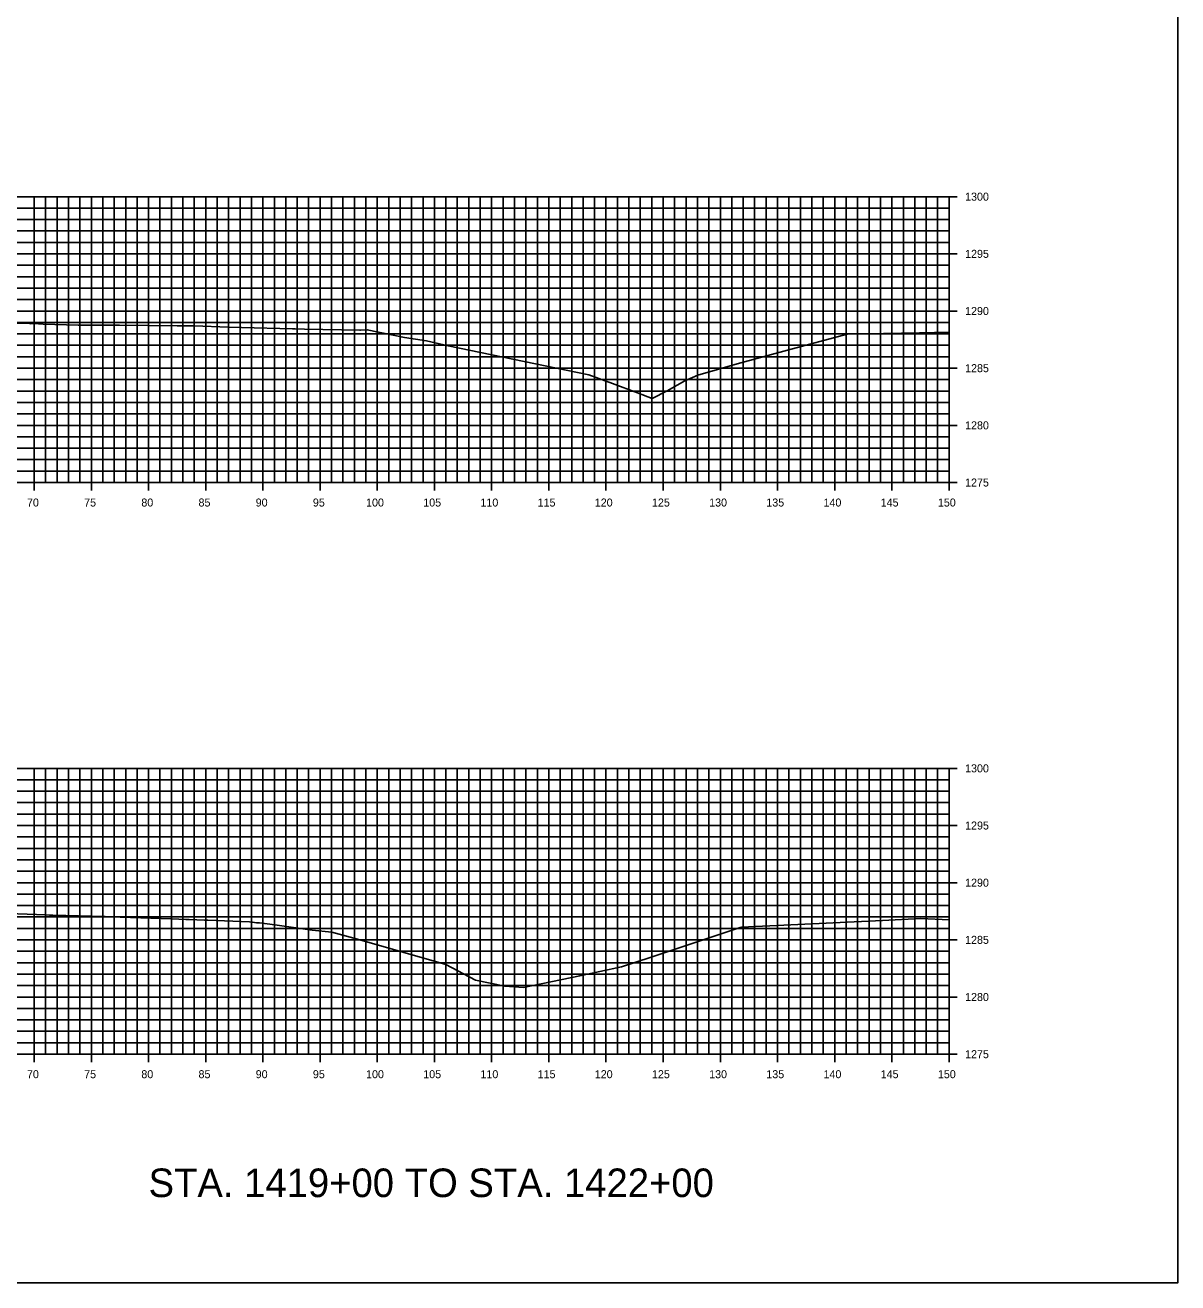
# Model space of a CAD drawing. Extents: x 674939 to 678919, y 750652 to 765176.
# Drawn here: x 678817.7 to 678918.5, y 757592.6 to 757702.6 of the extents above; entities that cross this region are included whole.
import ezdxf

# ---------------------------------------------------------------- set-up
doc = ezdxf.new("R2010")
doc.units = 0
for name, color, linetype in [('R_Axis', 7, 'Continuous'), ('R_Axis Annot', 7, 'Continuous'), ('R_Draft', 7, 'Continuous'), ('R_Exist Surface', 7, 'Continuous'), ('R_Grid', 7, 'Continuous'), ('R_No Plot', 7, 'Continuous')]:
    doc.layers.add(name, color=color, linetype=linetype)

msp = doc.modelspace()

# ---------------------------------------------------------------- linework, layer by layer
at = {"layer": 'R_Axis'}
for p, q in [((678899.23, 757687.55), (678897.83, 757687.55)), ((678898.53, 757662.55), (678898.53, 757687.55)), ((678899.23, 757682.55), (678897.83, 757682.55)), ((678899.23, 757677.55), (678897.83, 757677.55)), ((678899.23, 757672.55), (678897.83, 757672.55)), ((678899.23, 757667.55), (678897.83, 757667.55)), ((678598.53, 757662.55), (678898.53, 757662.55)), ((678818.53, 757661.85), (678818.53, 757663.25)), ((678823.53, 757661.85), (678823.53, 757663.25)), ((678828.53, 757661.85), (678828.53, 757663.25)), ((678833.53, 757661.85), (678833.53, 757663.25)), ((678838.53, 757661.85), (678838.53, 757663.25)), ((678843.53, 757661.85), (678843.53, 757663.25)), ((678848.53, 757661.85), (678848.53, 757663.25)), ((678853.53, 757661.85), (678853.53, 757663.25)), ((678858.53, 757661.85), (678858.53, 757663.25)), ((678863.53, 757661.85), (678863.53, 757663.25)), ((678868.53, 757661.85), (678868.53, 757663.25)), ((678873.53, 757661.85), (678873.53, 757663.25)), ((678878.53, 757661.85), (678878.53, 757663.25)), ((678883.53, 757661.85), (678883.53, 757663.25)), ((678888.53, 757661.85), (678888.53, 757663.25)), ((678893.53, 757661.85), (678893.53, 757663.25)), ((678899.23, 757662.55), (678897.83, 757662.55)), ((678898.53, 757661.85), (678898.53, 757663.25)), ((678899.23, 757637.55), (678897.83, 757637.55)), ((678898.53, 757612.55), (678898.53, 757637.55)), ((678899.23, 757632.55), (678897.83, 757632.55)), ((678899.23, 757627.55), (678897.83, 757627.55)), ((678899.23, 757622.55), (678897.83, 757622.55)), ((678899.23, 757617.55), (678897.83, 757617.55)), ((678818.53, 757611.85), (678818.53, 757613.25)), ((678823.53, 757611.85), (678823.53, 757613.25)), ((678828.53, 757611.85), (678828.53, 757613.25)), ((678833.53, 757611.85), (678833.53, 757613.25)), ((678838.53, 757611.85), (678838.53, 757613.25)), ((678843.53, 757611.85), (678843.53, 757613.25)), ((678848.53, 757611.85), (678848.53, 757613.25)), ((678853.53, 757611.85), (678853.53, 757613.25)), ((678858.53, 757611.85), (678858.53, 757613.25)), ((678863.53, 757611.85), (678863.53, 757613.25)), ((678868.53, 757611.85), (678868.53, 757613.25)), ((678873.53, 757611.85), (678873.53, 757613.25)), ((678878.53, 757611.85), (678878.53, 757613.25)), ((678883.53, 757611.85), (678883.53, 757613.25)), ((678888.53, 757611.85), (678888.53, 757613.25)), ((678893.53, 757611.85), (678893.53, 757613.25)), ((678898.53, 757611.85), (678898.53, 757613.25)), ((678598.53, 757612.55), (678898.53, 757612.55)), ((678899.23, 757612.55), (678897.83, 757612.55))]:
    msp.add_line(p, q, dxfattribs=at)
at = {"layer": 'R_Exist Surface'}
for points in [[(678815.29, 757676.51), (678818.11, 757676.45), (678818.25, 757676.43), (678818.46, 757676.45), (678818.46, 757676.45), (678819.33, 757676.4), (678822.38, 757676.3), (678824.56, 757676.3), (678824.74, 757676.3), (678825.95, 757676.31), (678825.99, 757676.31), (678831.03, 757676.25), (678832.56, 757676.24), (678835.49, 757676.15), (678836.65, 757676.12), (678841.12, 757676), (678841.32, 757676), (678841.35, 757676), (678842.16, 757675.97), (678847, 757675.87), (678847.04, 757675.87), (678847.05, 757675.87), (678847.65, 757675.91), (678850.9, 757675.24), (678852.84, 757674.94), (678854.72, 757674.51), (678867.03, 757671.96), (678869.1, 757671.22), (678871.29, 757670.38), (678872.58, 757669.91), (678873.89, 757670.56), (678875.43, 757671.43), (678876.57, 757671.95), (678879.99, 757672.94), (678884.39, 757674.13), (678889.61, 757675.53), (678895.95, 757675.65), (678898.53, 757675.71)], [(678816.27, 757624.85), (678819.54, 757624.73), (678819.87, 757624.72), (678820.16, 757624.71), (678824.68, 757624.58), (678824.75, 757624.58), (678825.15, 757624.56), (678830.54, 757624.39), (678831.19, 757624.36), (678831.78, 757624.34), (678832.02, 757624.34), (678832.09, 757624.33), (678833.41, 757624.27), (678833.52, 757624.27), (678833.7, 757624.26), (678837.36, 757624.12), (678837.49, 757624.11), (678837.57, 757624.11), (678837.62, 757624.11), (678837.97, 757624.05), (678838.07, 757624.05), (678838.12, 757624.05), (678838.22, 757624.04), (678839.58, 757623.86), (678842.83, 757623.41), (678844.55, 757623.21), (678846.8, 757622.61), (678854.53, 757620.4), (678857.11, 757619.01), (678859.68, 757618.49), (678861.31, 757618.38), (678866.24, 757619.41), (678867.98, 757619.77), (678869.88, 757620.2), (678872.49, 757621.04), (678880.25, 757623.63), (678880.39, 757623.67), (678892.72, 757624.24), (678896.05, 757624.42), (678898.53, 757624.31)]]:
    msp.add_lwpolyline(points, dxfattribs=at)
at = {"layer": 'R_Grid'}
for p, q in [((678598.53, 757687.55), (678898.53, 757687.55)), ((678818.53, 757662.55), (678818.53, 757687.55)), ((678819.53, 757662.55), (678819.53, 757687.55)), ((678820.53, 757662.55), (678820.53, 757687.55)), ((678821.53, 757662.55), (678821.53, 757687.55)), ((678822.53, 757662.55), (678822.53, 757687.55)), ((678823.53, 757662.55), (678823.53, 757687.55)), ((678824.53, 757662.55), (678824.53, 757687.55)), ((678825.53, 757662.55), (678825.53, 757687.55)), ((678826.53, 757662.55), (678826.53, 757687.55)), ((678827.53, 757662.55), (678827.53, 757687.55)), ((678828.53, 757662.55), (678828.53, 757687.55)), ((678829.53, 757662.55), (678829.53, 757687.55)), ((678830.53, 757662.55), (678830.53, 757687.55)), ((678831.53, 757662.55), (678831.53, 757687.55)), ((678832.53, 757662.55), (678832.53, 757687.55)), ((678833.53, 757662.55), (678833.53, 757687.55)), ((678834.53, 757662.55), (678834.53, 757687.55)), ((678835.53, 757662.55), (678835.53, 757687.55)), ((678836.53, 757662.55), (678836.53, 757687.55)), ((678837.53, 757662.55), (678837.53, 757687.55)), ((678838.53, 757662.55), (678838.53, 757687.55)), ((678839.53, 757662.55), (678839.53, 757687.55)), ((678840.53, 757662.55), (678840.53, 757687.55)), ((678841.53, 757662.55), (678841.53, 757687.55)), ((678842.53, 757662.55), (678842.53, 757687.55)), ((678843.53, 757662.55), (678843.53, 757687.55)), ((678844.53, 757662.55), (678844.53, 757687.55)), ((678845.53, 757662.55), (678845.53, 757687.55)), ((678846.53, 757662.55), (678846.53, 757687.55)), ((678847.53, 757662.55), (678847.53, 757687.55)), ((678848.53, 757662.55), (678848.53, 757687.55)), ((678849.53, 757662.55), (678849.53, 757687.55)), ((678850.53, 757662.55), (678850.53, 757687.55)), ((678851.53, 757662.55), (678851.53, 757687.55)), ((678852.53, 757662.55), (678852.53, 757687.55)), ((678853.53, 757662.55), (678853.53, 757687.55)), ((678854.53, 757662.55), (678854.53, 757687.55)), ((678855.53, 757662.55), (678855.53, 757687.55)), ((678856.53, 757662.55), (678856.53, 757687.55)), ((678857.53, 757662.55), (678857.53, 757687.55)), ((678858.53, 757662.55), (678858.53, 757687.55)), ((678859.53, 757662.55), (678859.53, 757687.55)), ((678860.53, 757662.55), (678860.53, 757687.55)), ((678861.53, 757662.55), (678861.53, 757687.55)), ((678862.53, 757662.55), (678862.53, 757687.55)), ((678863.53, 757662.55), (678863.53, 757687.55)), ((678864.53, 757662.55), (678864.53, 757687.55)), ((678865.53, 757662.55), (678865.53, 757687.55)), ((678866.53, 757662.55), (678866.53, 757687.55)), ((678867.53, 757662.55), (678867.53, 757687.55)), ((678868.53, 757662.55), (678868.53, 757687.55)), ((678869.53, 757662.55), (678869.53, 757687.55)), ((678870.53, 757662.55), (678870.53, 757687.55)), ((678871.53, 757662.55), (678871.53, 757687.55)), ((678872.53, 757662.55), (678872.53, 757687.55)), ((678873.53, 757662.55), (678873.53, 757687.55)), ((678874.53, 757662.55), (678874.53, 757687.55)), ((678875.53, 757662.55), (678875.53, 757687.55)), ((678876.53, 757662.55), (678876.53, 757687.55)), ((678877.53, 757662.55), (678877.53, 757687.55)), ((678878.53, 757662.55), (678878.53, 757687.55)), ((678879.53, 757662.55), (678879.53, 757687.55)), ((678880.53, 757662.55), (678880.53, 757687.55)), ((678881.53, 757662.55), (678881.53, 757687.55)), ((678882.53, 757662.55), (678882.53, 757687.55)), ((678883.53, 757662.55), (678883.53, 757687.55)), ((678884.53, 757662.55), (678884.53, 757687.55)), ((678885.53, 757662.55), (678885.53, 757687.55)), ((678886.53, 757662.55), (678886.53, 757687.55)), ((678887.53, 757662.55), (678887.53, 757687.55)), ((678888.53, 757662.55), (678888.53, 757687.55)), ((678889.53, 757662.55), (678889.53, 757687.55)), ((678890.53, 757662.55), (678890.53, 757687.55)), ((678891.53, 757662.55), (678891.53, 757687.55)), ((678892.53, 757662.55), (678892.53, 757687.55)), ((678893.53, 757662.55), (678893.53, 757687.55)), ((678894.53, 757662.55), (678894.53, 757687.55)), ((678895.53, 757662.55), (678895.53, 757687.55)), ((678896.53, 757662.55), (678896.53, 757687.55)), ((678897.53, 757662.55), (678897.53, 757687.55)), ((678898.53, 757662.55), (678898.53, 757687.55)), ((678598.53, 757686.55), (678898.53, 757686.55)), ((678598.53, 757685.55), (678898.53, 757685.55)), ((678598.53, 757684.55), (678898.53, 757684.55)), ((678598.53, 757683.55), (678898.53, 757683.55)), ((678598.53, 757682.55), (678898.53, 757682.55)), ((678598.53, 757681.55), (678898.53, 757681.55)), ((678598.53, 757680.55), (678898.53, 757680.55)), ((678598.53, 757679.55), (678898.53, 757679.55)), ((678598.53, 757678.55), (678898.53, 757678.55)), ((678598.53, 757677.55), (678898.53, 757677.55)), ((678598.53, 757676.55), (678898.53, 757676.55)), ((678598.53, 757675.55), (678898.53, 757675.55)), ((678598.53, 757674.55), (678898.53, 757674.55)), ((678598.53, 757673.55), (678898.53, 757673.55)), ((678598.53, 757672.55), (678898.53, 757672.55)), ((678598.53, 757671.55), (678898.53, 757671.55)), ((678598.53, 757670.55), (678898.53, 757670.55)), ((678598.53, 757669.55), (678898.53, 757669.55)), ((678598.53, 757668.55), (678898.53, 757668.55)), ((678598.53, 757667.55), (678898.53, 757667.55)), ((678598.53, 757666.55), (678898.53, 757666.55)), ((678598.53, 757665.55), (678898.53, 757665.55)), ((678598.53, 757664.55), (678898.53, 757664.55)), ((678598.53, 757663.55), (678898.53, 757663.55)), ((678598.53, 757662.55), (678898.53, 757662.55)), ((678598.53, 757637.55), (678898.53, 757637.55)), ((678818.53, 757612.55), (678818.53, 757637.55)), ((678819.53, 757612.55), (678819.53, 757637.55)), ((678820.53, 757612.55), (678820.53, 757637.55)), ((678821.53, 757612.55), (678821.53, 757637.55)), ((678822.53, 757612.55), (678822.53, 757637.55)), ((678823.53, 757612.55), (678823.53, 757637.55)), ((678824.53, 757612.55), (678824.53, 757637.55)), ((678825.53, 757612.55), (678825.53, 757637.55)), ((678826.53, 757612.55), (678826.53, 757637.55)), ((678827.53, 757612.55), (678827.53, 757637.55)), ((678828.53, 757612.55), (678828.53, 757637.55)), ((678829.53, 757612.55), (678829.53, 757637.55)), ((678830.53, 757612.55), (678830.53, 757637.55)), ((678831.53, 757612.55), (678831.53, 757637.55)), ((678832.53, 757612.55), (678832.53, 757637.55)), ((678833.53, 757612.55), (678833.53, 757637.55)), ((678834.53, 757612.55), (678834.53, 757637.55)), ((678835.53, 757612.55), (678835.53, 757637.55)), ((678836.53, 757612.55), (678836.53, 757637.55)), ((678837.53, 757612.55), (678837.53, 757637.55)), ((678838.53, 757612.55), (678838.53, 757637.55)), ((678839.53, 757612.55), (678839.53, 757637.55)), ((678840.53, 757612.55), (678840.53, 757637.55)), ((678841.53, 757612.55), (678841.53, 757637.55)), ((678842.53, 757612.55), (678842.53, 757637.55)), ((678843.53, 757612.55), (678843.53, 757637.55)), ((678844.53, 757612.55), (678844.53, 757637.55)), ((678845.53, 757612.55), (678845.53, 757637.55)), ((678846.53, 757612.55), (678846.53, 757637.55)), ((678847.53, 757612.55), (678847.53, 757637.55)), ((678848.53, 757612.55), (678848.53, 757637.55)), ((678849.53, 757612.55), (678849.53, 757637.55)), ((678850.53, 757612.55), (678850.53, 757637.55)), ((678851.53, 757612.55), (678851.53, 757637.55)), ((678852.53, 757612.55), (678852.53, 757637.55)), ((678853.53, 757612.55), (678853.53, 757637.55)), ((678854.53, 757612.55), (678854.53, 757637.55)), ((678855.53, 757612.55), (678855.53, 757637.55)), ((678856.53, 757612.55), (678856.53, 757637.55)), ((678857.53, 757612.55), (678857.53, 757637.55)), ((678858.53, 757612.55), (678858.53, 757637.55)), ((678859.53, 757612.55), (678859.53, 757637.55)), ((678860.53, 757612.55), (678860.53, 757637.55)), ((678861.53, 757612.55), (678861.53, 757637.55)), ((678862.53, 757612.55), (678862.53, 757637.55)), ((678863.53, 757612.55), (678863.53, 757637.55)), ((678864.53, 757612.55), (678864.53, 757637.55)), ((678865.53, 757612.55), (678865.53, 757637.55)), ((678866.53, 757612.55), (678866.53, 757637.55)), ((678867.53, 757612.55), (678867.53, 757637.55)), ((678868.53, 757612.55), (678868.53, 757637.55)), ((678869.53, 757612.55), (678869.53, 757637.55)), ((678870.53, 757612.55), (678870.53, 757637.55)), ((678871.53, 757612.55), (678871.53, 757637.55)), ((678872.53, 757612.55), (678872.53, 757637.55)), ((678873.53, 757612.55), (678873.53, 757637.55)), ((678874.53, 757612.55), (678874.53, 757637.55)), ((678875.53, 757612.55), (678875.53, 757637.55)), ((678876.53, 757612.55), (678876.53, 757637.55)), ((678877.53, 757612.55), (678877.53, 757637.55)), ((678878.53, 757612.55), (678878.53, 757637.55)), ((678879.53, 757612.55), (678879.53, 757637.55)), ((678880.53, 757612.55), (678880.53, 757637.55)), ((678881.53, 757612.55), (678881.53, 757637.55)), ((678882.53, 757612.55), (678882.53, 757637.55)), ((678883.53, 757612.55), (678883.53, 757637.55)), ((678884.53, 757612.55), (678884.53, 757637.55)), ((678885.53, 757612.55), (678885.53, 757637.55)), ((678886.53, 757612.55), (678886.53, 757637.55)), ((678887.53, 757612.55), (678887.53, 757637.55)), ((678888.53, 757612.55), (678888.53, 757637.55)), ((678889.53, 757612.55), (678889.53, 757637.55)), ((678890.53, 757612.55), (678890.53, 757637.55)), ((678891.53, 757612.55), (678891.53, 757637.55)), ((678892.53, 757612.55), (678892.53, 757637.55)), ((678893.53, 757612.55), (678893.53, 757637.55)), ((678894.53, 757612.55), (678894.53, 757637.55)), ((678895.53, 757612.55), (678895.53, 757637.55)), ((678896.53, 757612.55), (678896.53, 757637.55)), ((678897.53, 757612.55), (678897.53, 757637.55)), ((678898.53, 757612.55), (678898.53, 757637.55)), ((678598.53, 757636.55), (678898.53, 757636.55)), ((678598.53, 757635.55), (678898.53, 757635.55)), ((678598.53, 757634.55), (678898.53, 757634.55)), ((678598.53, 757633.55), (678898.53, 757633.55)), ((678598.53, 757632.55), (678898.53, 757632.55)), ((678598.53, 757631.55), (678898.53, 757631.55)), ((678598.53, 757630.55), (678898.53, 757630.55)), ((678598.53, 757629.55), (678898.53, 757629.55)), ((678598.53, 757628.55), (678898.53, 757628.55)), ((678598.53, 757627.55), (678898.53, 757627.55)), ((678598.53, 757626.55), (678898.53, 757626.55)), ((678598.53, 757625.55), (678898.53, 757625.55)), ((678598.53, 757624.55), (678898.53, 757624.55)), ((678598.53, 757623.55), (678898.53, 757623.55)), ((678598.53, 757622.55), (678898.53, 757622.55)), ((678598.53, 757621.55), (678898.53, 757621.55)), ((678598.53, 757620.55), (678898.53, 757620.55)), ((678598.53, 757619.55), (678898.53, 757619.55)), ((678598.53, 757618.55), (678898.53, 757618.55)), ((678598.53, 757617.55), (678898.53, 757617.55)), ((678598.53, 757616.55), (678898.53, 757616.55)), ((678598.53, 757615.55), (678898.53, 757615.55)), ((678598.53, 757614.55), (678898.53, 757614.55)), ((678598.53, 757613.55), (678898.53, 757613.55)), ((678598.53, 757612.55), (678898.53, 757612.55))]:
    msp.add_line(p, q, dxfattribs=at)
at = {"layer": 'R_No Plot'}
msp.add_lwpolyline([(678578.53, 757592.55), (678918.53, 757592.55), (678918.53, 757812.55), (678578.53, 757812.55)], close=True, dxfattribs=at)

# ---------------------------------------------------------------- texts
at = {"layer": 'R_Axis Annot'}
for s, p in [('1300', (678899.93, 757687.2)), ('1295', (678899.93, 757682.2)), ('1290', (678899.93, 757677.2)), ('1285', (678899.93, 757672.2)), ('1280', (678899.93, 757667.2)), ('1275', (678899.93, 757662.2)), ('70', (678817.9, 757660.45)), ('75', (678822.9, 757660.45)), ('80', (678827.9, 757660.45)), ('85', (678832.9, 757660.45)), ('90', (678837.9, 757660.45)), ('95', (678842.9, 757660.45)), ('100', (678847.55, 757660.45)), ('105', (678852.55, 757660.45)), ('110', (678857.55, 757660.45)), ('115', (678862.55, 757660.45)), ('120', (678867.55, 757660.45)), ('125', (678872.55, 757660.45)), ('130', (678877.55, 757660.45)), ('135', (678882.55, 757660.45)), ('140', (678887.55, 757660.45)), ('145', (678892.55, 757660.45)), ('150', (678897.55, 757660.45)), ('1300', (678899.93, 757637.2)), ('1295', (678899.93, 757632.2)), ('1290', (678899.93, 757627.2)), ('1285', (678899.93, 757622.2)), ('1280', (678899.93, 757617.2)), ('1275', (678899.93, 757612.2)), ('70', (678817.9, 757610.45)), ('75', (678822.9, 757610.45)), ('80', (678827.9, 757610.45)), ('85', (678832.9, 757610.45)), ('90', (678837.9, 757610.45)), ('95', (678842.9, 757610.45)), ('100', (678847.55, 757610.45)), ('105', (678852.55, 757610.45)), ('110', (678857.55, 757610.45)), ('115', (678862.55, 757610.45)), ('120', (678867.55, 757610.45)), ('125', (678872.55, 757610.45)), ('130', (678877.55, 757610.45)), ('135', (678882.55, 757610.45)), ('140', (678887.55, 757610.45)), ('145', (678892.55, 757610.45)), ('150', (678897.55, 757610.45))]:
    msp.add_text(s, height=0.7, dxfattribs=at).set_placement(p)
at = {"layer": 'R_Draft'}
msp.add_text('STA. 1419+00 TO STA. 1422+00', height=2.5, dxfattribs=at).set_placement((678828.53, 757600.05))

doc.saveas('drawing.dxf')
